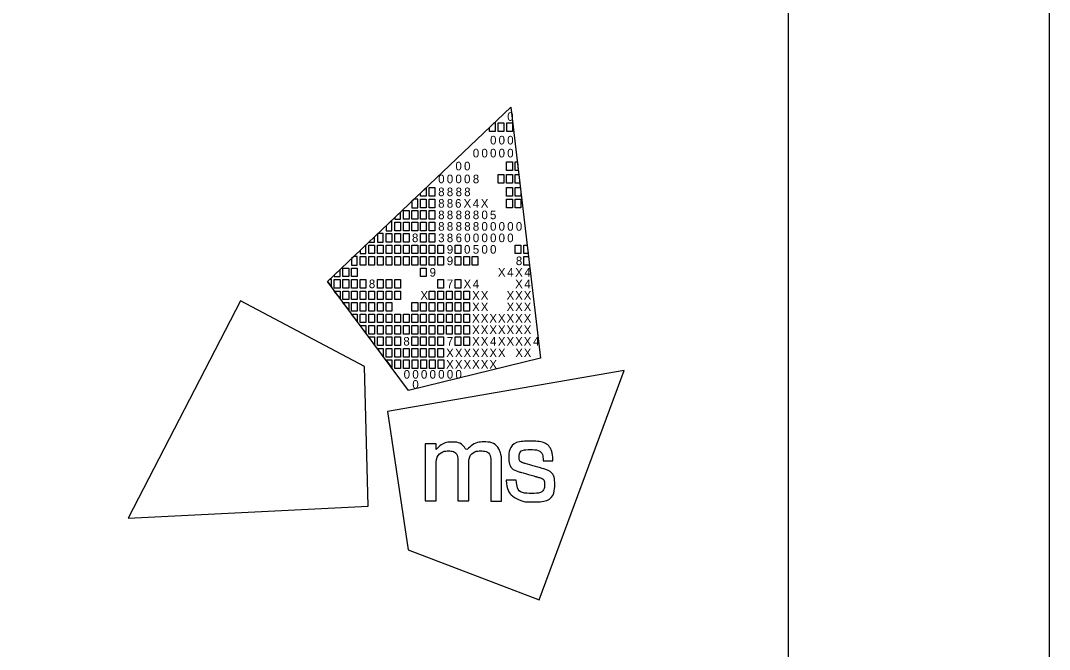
# Model space of a CAD drawing. Extents: x 22.7 to 63.9, y 8.1 to 30.1.
# Drawn here: x 54.689 to 56.659, y 11.605 to 12.81 of the extents above; entities that cross this region are included whole.
import ezdxf

# ---------------------------------------------------------------- set-up
doc = ezdxf.new("R2010")
doc.units = 0
for name, color, linetype in [('SH_Border', 7, 'Continuous'), ('SH_Cut_Line', 7, 'Continuous'), ('SH_Data', 7, 'Continuous')]:
    doc.layers.add(name, color=color, linetype=linetype)

msp = doc.modelspace()

# ---------------------------------------------------------------- linework, layer by layer
at = {"layer": 'SH_Border'}
for p, q in [((55.2765, 12.3096), (55.6277, 12.6438)), ((55.6277, 12.6438), (55.6277, 12.6438)), ((55.6277, 12.6438), (55.6842, 12.1628)), ((55.4319, 12.1007), (55.2765, 12.3096)), ((55.6842, 12.1628), (55.4319, 12.1007))]:
    msp.add_line(p, q, dxfattribs=at)
for points in [[(24.1589, 29.5577), (56.1589, 29.5577), (56.1589, 8.5577), (24.1589, 8.5577)], [(55.5868, 12.6049), (55.5958, 12.6135), (55.5978, 12.6135), (55.5978, 12.5969), (55.5868, 12.5969)], [(55.6033, 12.6135), (55.6143, 12.6135), (55.6143, 12.5969), (55.6033, 12.5969)], [(55.6198, 12.6135), (55.6308, 12.6135), (55.6308, 12.5969), (55.6198, 12.5969)], [(55.6195, 12.5391), (55.6305, 12.5391), (55.6305, 12.5226), (55.6195, 12.5226)], [(55.636, 12.5391), (55.64, 12.5391), (55.6419, 12.5226), (55.636, 12.5226)], [(55.603, 12.5144), (55.614, 12.5144), (55.614, 12.4979), (55.603, 12.4979)], [(55.6195, 12.5144), (55.6305, 12.5144), (55.6305, 12.4979), (55.6195, 12.4979)], [(55.636, 12.5144), (55.6429, 12.5144), (55.6448, 12.4979), (55.636, 12.4979)], [(55.4543, 12.4788), (55.4653, 12.4893), (55.4653, 12.4731), (55.4543, 12.4731)], [(55.4712, 12.4896), (55.4822, 12.4896), (55.4822, 12.4731), (55.4712, 12.4731)], [(55.6195, 12.4896), (55.6305, 12.4896), (55.6305, 12.4731), (55.6195, 12.4731)], [(55.636, 12.4896), (55.6458, 12.4896), (55.647, 12.4795), (55.647, 12.4731), (55.636, 12.4731)], [(55.4547, 12.4676), (55.4657, 12.4676), (55.4657, 12.4511), (55.4547, 12.4511)], [(55.4712, 12.4676), (55.4822, 12.4676), (55.4822, 12.4511), (55.4712, 12.4511)], [(55.6195, 12.4676), (55.6305, 12.4676), (55.6305, 12.4511), (55.6195, 12.4511)], [(55.636, 12.4676), (55.647, 12.4676), (55.647, 12.4511), (55.636, 12.4511)], [(55.4217, 12.4456), (55.4327, 12.4456), (55.4327, 12.4291), (55.4217, 12.4291)], [(55.4382, 12.4456), (55.4492, 12.4456), (55.4492, 12.4291), (55.4382, 12.4291)], [(55.4547, 12.4456), (55.4657, 12.4456), (55.4657, 12.4291), (55.4547, 12.4291)], [(55.4712, 12.4456), (55.4822, 12.4456), (55.4822, 12.4291), (55.4712, 12.4291)], [(55.4051, 12.4236), (55.4162, 12.4236), (55.4162, 12.407), (55.4051, 12.407)], [(55.4217, 12.4236), (55.4327, 12.4236), (55.4327, 12.407), (55.4217, 12.407)], [(55.4382, 12.4236), (55.4492, 12.4236), (55.4492, 12.407), (55.4382, 12.407)], [(55.4547, 12.4236), (55.4657, 12.4236), (55.4657, 12.407), (55.4547, 12.407)], [(55.4712, 12.4236), (55.4822, 12.4236), (55.4822, 12.407), (55.4712, 12.407)], [(55.3886, 12.4015), (55.3996, 12.4015), (55.3996, 12.385), (55.3886, 12.385)], [(55.4051, 12.4015), (55.4162, 12.4015), (55.4162, 12.385), (55.4051, 12.385)], [(55.4217, 12.4015), (55.4327, 12.4015), (55.4327, 12.385), (55.4217, 12.385)], [(55.4547, 12.4015), (55.4657, 12.4015), (55.4657, 12.385), (55.4547, 12.385)], [(55.4712, 12.4015), (55.4822, 12.4015), (55.4822, 12.385), (55.4712, 12.385)], [(55.3556, 12.3795), (55.3666, 12.3795), (55.3666, 12.363), (55.3556, 12.363)], [(55.3721, 12.3795), (55.3831, 12.3795), (55.3831, 12.363), (55.3721, 12.363)], [(55.3886, 12.3795), (55.3996, 12.3795), (55.3996, 12.363), (55.3886, 12.363)], [(55.4051, 12.3795), (55.4162, 12.3795), (55.4162, 12.363), (55.4051, 12.363)], [(55.4217, 12.3795), (55.4327, 12.3795), (55.4327, 12.363), (55.4217, 12.363)], [(55.4382, 12.3795), (55.4492, 12.3795), (55.4492, 12.363), (55.4382, 12.363)], [(55.4547, 12.3795), (55.4657, 12.3795), (55.4657, 12.363), (55.4547, 12.363)], [(55.4712, 12.3795), (55.4822, 12.3795), (55.4822, 12.363), (55.4712, 12.363)], [(55.4877, 12.3795), (55.4987, 12.3795), (55.4987, 12.363), (55.4877, 12.363)], [(55.5207, 12.3795), (55.5317, 12.3795), (55.5317, 12.363), (55.5207, 12.363)], [(55.636, 12.3795), (55.647, 12.3795), (55.647, 12.363), (55.636, 12.363)], [(55.6525, 12.3795), (55.6587, 12.3795), (55.6607, 12.363), (55.6525, 12.363)], [(55.3391, 12.3575), (55.3501, 12.3575), (55.3501, 12.341), (55.3391, 12.341)], [(55.3556, 12.3575), (55.3666, 12.3575), (55.3666, 12.341), (55.3556, 12.341)], [(55.3721, 12.3575), (55.3831, 12.3575), (55.3831, 12.341), (55.3721, 12.341)], [(55.3886, 12.3575), (55.3996, 12.3575), (55.3996, 12.341), (55.3886, 12.341)], [(55.4051, 12.3575), (55.4162, 12.3575), (55.4162, 12.341), (55.4051, 12.341)], [(55.4217, 12.3575), (55.4327, 12.3575), (55.4327, 12.341), (55.4217, 12.341)], [(55.4382, 12.3575), (55.4492, 12.3575), (55.4492, 12.341), (55.4382, 12.341)], [(55.4547, 12.3575), (55.4657, 12.3575), (55.4657, 12.341), (55.4547, 12.341)], [(55.4712, 12.3575), (55.4822, 12.3575), (55.4822, 12.341), (55.4712, 12.341)], [(55.4877, 12.3575), (55.4987, 12.3575), (55.4987, 12.341), (55.4877, 12.341)], [(55.5207, 12.3575), (55.5317, 12.3575), (55.5317, 12.341), (55.5207, 12.341)], [(55.5373, 12.3575), (55.5483, 12.3575), (55.5483, 12.341), (55.5373, 12.341)], [(55.5536, 12.3575), (55.5646, 12.3575), (55.5646, 12.341), (55.5536, 12.341)], [(55.6525, 12.3575), (55.6613, 12.3575), (55.6633, 12.341), (55.6525, 12.341)], [(55.3061, 12.3355), (55.3171, 12.3355), (55.3171, 12.319), (55.3061, 12.319)], [(55.3226, 12.3355), (55.3336, 12.3355), (55.3336, 12.319), (55.3226, 12.319)], [(55.4547, 12.3355), (55.4657, 12.3355), (55.4657, 12.319), (55.4547, 12.319)], [(55.2895, 12.3135), (55.3006, 12.3135), (55.3006, 12.2969), (55.2895, 12.2969)], [(55.3061, 12.3135), (55.3171, 12.3135), (55.3171, 12.2969), (55.3061, 12.2969)], [(55.3226, 12.3135), (55.3336, 12.3135), (55.3336, 12.2969), (55.3226, 12.2969)], [(55.3391, 12.3135), (55.3501, 12.3135), (55.3501, 12.2969), (55.3391, 12.2969)], [(55.3721, 12.3135), (55.3831, 12.3135), (55.3831, 12.2969), (55.3721, 12.2969)], [(55.3886, 12.3135), (55.3996, 12.3135), (55.3996, 12.2969), (55.3886, 12.2969)], [(55.4051, 12.3135), (55.4162, 12.3135), (55.4162, 12.2969), (55.4051, 12.2969)], [(55.4877, 12.3135), (55.4987, 12.3135), (55.4987, 12.2969), (55.4877, 12.2969)], [(55.5207, 12.3135), (55.5317, 12.3135), (55.5317, 12.2969), (55.5207, 12.2969)], [(55.2895, 12.2914), (55.3006, 12.2914), (55.3006, 12.2777)], [(55.3061, 12.2914), (55.3171, 12.2914), (55.3171, 12.2749), (55.3061, 12.2749)], [(55.3226, 12.2914), (55.3336, 12.2914), (55.3336, 12.2749), (55.3226, 12.2749)], [(55.3391, 12.2914), (55.3501, 12.2914), (55.3501, 12.2749), (55.3391, 12.2749)], [(55.3556, 12.2914), (55.3666, 12.2914), (55.3666, 12.2749), (55.3556, 12.2749)], [(55.3721, 12.2914), (55.3831, 12.2914), (55.3831, 12.2749), (55.3721, 12.2749)], [(55.3886, 12.2914), (55.3996, 12.2914), (55.3996, 12.2749), (55.3886, 12.2749)], [(55.4051, 12.2914), (55.4162, 12.2914), (55.4162, 12.2749), (55.4051, 12.2749)], [(55.4712, 12.2914), (55.4822, 12.2914), (55.4822, 12.2749), (55.4712, 12.2749)], [(55.4877, 12.2914), (55.4987, 12.2914), (55.4987, 12.2749), (55.4877, 12.2749)], [(55.5042, 12.2914), (55.5152, 12.2914), (55.5152, 12.2749), (55.5042, 12.2749)], [(55.5207, 12.2914), (55.5317, 12.2914), (55.5317, 12.2749), (55.5207, 12.2749)], [(55.5373, 12.2914), (55.5483, 12.2914), (55.5483, 12.2749), (55.5373, 12.2749)], [(55.3061, 12.2694), (55.3171, 12.2694), (55.3171, 12.2557)], [(55.3226, 12.2694), (55.3336, 12.2694), (55.3336, 12.2529), (55.3226, 12.2529)], [(55.3391, 12.2694), (55.3501, 12.2694), (55.3501, 12.2529), (55.3391, 12.2529)], [(55.3556, 12.2694), (55.3666, 12.2694), (55.3666, 12.2529), (55.3556, 12.2529)], [(55.3721, 12.2694), (55.3831, 12.2694), (55.3831, 12.2529), (55.3721, 12.2529)], [(55.3886, 12.2694), (55.3996, 12.2694), (55.3996, 12.2529), (55.3886, 12.2529)], [(55.4382, 12.2694), (55.4492, 12.2694), (55.4492, 12.2529), (55.4382, 12.2529)], [(55.4547, 12.2694), (55.4657, 12.2694), (55.4657, 12.2529), (55.4547, 12.2529)], [(55.4712, 12.2694), (55.4822, 12.2694), (55.4822, 12.2529), (55.4712, 12.2529)], [(55.4877, 12.2694), (55.4987, 12.2694), (55.4987, 12.2529), (55.4877, 12.2529)], [(55.5042, 12.2694), (55.5152, 12.2694), (55.5152, 12.2529), (55.5042, 12.2529)], [(55.5207, 12.2694), (55.5317, 12.2694), (55.5317, 12.2529), (55.5207, 12.2529)], [(55.5373, 12.2694), (55.5483, 12.2694), (55.5483, 12.2529), (55.5373, 12.2529)], [(55.3226, 12.2474), (55.3336, 12.2474), (55.3336, 12.2336)], [(55.3336, 12.2474), (55.3336, 12.2474), (55.3336, 12.2474)], [(55.3391, 12.2474), (55.3501, 12.2474), (55.3501, 12.2309), (55.3391, 12.2309)], [(55.3556, 12.2474), (55.3666, 12.2474), (55.3666, 12.2309), (55.3556, 12.2309)], [(55.3721, 12.2474), (55.3831, 12.2474), (55.3831, 12.2309), (55.3721, 12.2309)], [(55.3886, 12.2474), (55.3996, 12.2474), (55.3996, 12.2309), (55.3886, 12.2309)], [(55.4051, 12.2474), (55.4162, 12.2474), (55.4162, 12.2309), (55.4051, 12.2309)], [(55.4217, 12.2474), (55.4327, 12.2474), (55.4327, 12.2309), (55.4217, 12.2309)], [(55.4382, 12.2474), (55.4492, 12.2474), (55.4492, 12.2309), (55.4382, 12.2309)], [(55.4547, 12.2474), (55.4657, 12.2474), (55.4657, 12.2309), (55.4547, 12.2309)], [(55.4712, 12.2474), (55.4822, 12.2474), (55.4822, 12.2309), (55.4712, 12.2309)], [(55.4877, 12.2474), (55.4987, 12.2474), (55.4987, 12.2309), (55.4877, 12.2309)], [(55.5042, 12.2474), (55.5152, 12.2474), (55.5152, 12.2309), (55.5042, 12.2309)], [(55.5207, 12.2474), (55.5317, 12.2474), (55.5317, 12.2309), (55.5207, 12.2309)], [(55.5373, 12.2474), (55.5483, 12.2474), (55.5483, 12.2309), (55.5373, 12.2309)], [(55.3391, 12.2254), (55.3501, 12.2254), (55.3501, 12.2116)], [(55.3556, 12.2254), (55.3666, 12.2254), (55.3666, 12.2089), (55.3556, 12.2089)], [(55.3721, 12.2254), (55.3831, 12.2254), (55.3831, 12.2089), (55.3721, 12.2089)], [(55.3886, 12.2254), (55.3996, 12.2254), (55.3996, 12.2089), (55.3886, 12.2089)], [(55.4051, 12.2254), (55.4162, 12.2254), (55.4162, 12.2089), (55.4051, 12.2089)], [(55.4217, 12.2254), (55.4327, 12.2254), (55.4327, 12.2089), (55.4217, 12.2089)], [(55.4382, 12.2254), (55.4492, 12.2254), (55.4492, 12.2089), (55.4382, 12.2089)], [(55.4547, 12.2254), (55.4657, 12.2254), (55.4657, 12.2089), (55.4547, 12.2089)], [(55.4712, 12.2254), (55.4822, 12.2254), (55.4822, 12.2089), (55.4712, 12.2089)], [(55.4877, 12.2254), (55.4987, 12.2254), (55.4987, 12.2089), (55.4877, 12.2089)], [(55.5042, 12.2254), (55.5152, 12.2254), (55.5152, 12.2089), (55.5042, 12.2089)], [(55.5207, 12.2254), (55.5317, 12.2254), (55.5317, 12.2089), (55.5207, 12.2089)], [(55.5373, 12.2254), (55.5483, 12.2254), (55.5483, 12.2089), (55.5373, 12.2089)], [(55.3667, 12.1882), (55.3555, 12.2034), (55.3667, 12.2034)], [(55.3721, 12.2034), (55.3831, 12.2034), (55.3831, 12.1869), (55.3721, 12.1869)], [(55.3886, 12.2034), (55.3996, 12.2034), (55.3996, 12.1869), (55.3886, 12.1869)], [(55.4051, 12.2034), (55.4162, 12.2034), (55.4162, 12.1869), (55.4051, 12.1869)], [(55.4382, 12.2034), (55.4492, 12.2034), (55.4492, 12.1869), (55.4382, 12.1869)], [(55.4547, 12.2034), (55.4657, 12.2034), (55.4657, 12.1869), (55.4547, 12.1869)], [(55.4712, 12.2034), (55.4822, 12.2034), (55.4822, 12.1869), (55.4712, 12.1869)], [(55.4877, 12.2034), (55.4987, 12.2034), (55.4987, 12.1869), (55.4877, 12.1869)], [(55.5207, 12.2034), (55.5317, 12.2034), (55.5317, 12.1869), (55.5207, 12.1869)], [(55.5373, 12.2034), (55.5483, 12.2034), (55.5483, 12.1869), (55.5373, 12.1869)], [(55.3829, 12.1659), (55.3721, 12.1814), (55.3831, 12.1814)], [(55.3886, 12.1813), (55.3996, 12.1813), (55.3996, 12.1648), (55.3886, 12.1648)], [(55.4051, 12.1813), (55.4162, 12.1813), (55.4162, 12.1648), (55.4051, 12.1648)], [(55.4217, 12.1813), (55.4327, 12.1813), (55.4327, 12.1648), (55.4217, 12.1648)], [(55.4382, 12.1813), (55.4492, 12.1813), (55.4492, 12.1648), (55.4382, 12.1648)], [(55.4547, 12.1813), (55.4657, 12.1813), (55.4657, 12.1648), (55.4547, 12.1648)], [(55.4712, 12.1813), (55.4822, 12.1813), (55.4822, 12.1648), (55.4712, 12.1648)], [(55.4877, 12.1813), (55.4987, 12.1813), (55.4987, 12.1648), (55.4877, 12.1648)], [(55.3891, 12.1594), (55.3996, 12.1594), (55.3997, 12.1452)], [(55.4052, 12.1594), (55.4162, 12.1594), (55.4162, 12.1429), (55.4052, 12.1429)], [(55.4219, 12.1594), (55.4329, 12.1594), (55.4329, 12.1429), (55.4219, 12.1429)], [(55.4383, 12.1594), (55.4493, 12.1594), (55.4493, 12.1429), (55.4383, 12.1429)], [(55.4549, 12.1594), (55.466, 12.1594), (55.466, 12.1429), (55.4549, 12.1429)], [(55.4719, 12.1593), (55.4829, 12.1593), (55.4829, 12.1428), (55.4719, 12.1428)], [(55.4885, 12.1593), (55.4995, 12.1593), (55.4995, 12.1428), (55.4885, 12.1428)]]:
    msp.add_lwpolyline(points, close=True, dxfattribs=at)
for points in [[(55.4492, 12.4676), (55.4425, 12.4676), (55.4382, 12.4635), (55.4382, 12.4511), (55.4492, 12.4511), (55.4492, 12.4676)], [(55.4162, 12.4425), (55.4051, 12.4321), (55.4051, 12.4291), (55.4162, 12.4291), (55.4162, 12.4425)], [(55.3996, 12.4268), (55.3886, 12.4163), (55.3886, 12.407), (55.3996, 12.407), (55.3996, 12.4268)], [(55.3666, 12.3954), (55.3557, 12.385), (55.3666, 12.385), (55.3666, 12.3954)], [(55.3831, 12.4015), (55.3731, 12.4015), (55.3721, 12.4006), (55.3721, 12.385), (55.3831, 12.385), (55.3831, 12.4015)], [(55.3501, 12.3797), (55.3391, 12.3692), (55.3391, 12.363), (55.3501, 12.363), (55.3501, 12.3797)], [(55.3336, 12.3575), (55.3268, 12.3575), (55.3226, 12.3535), (55.3226, 12.341), (55.3336, 12.341), (55.3336, 12.3575)], [(55.3006, 12.3325), (55.2895, 12.3221), (55.2895, 12.319), (55.3006, 12.319), (55.3006, 12.3325)], [(55.284, 12.3135), (55.2805, 12.3135), (55.2765, 12.3096), (55.284, 12.2994), (55.284, 12.3135)], [(55.1101, 12.2725), (54.8948, 11.8565), (55.3545, 11.8791), (55.3473, 12.1468), (55.1101, 12.2725)], [(55.6818, 11.6999), (55.8448, 12.1391), (55.3913, 12.0606), (55.4311, 11.7958), (55.6818, 11.6999)]]:
    msp.add_lwpolyline(points, dxfattribs=at)
for points in [[(55.4637, 11.8892), (55.4637, 11.8892), (55.4637, 11.9986), (55.4637, 11.9986), (55.4637, 11.9986), (55.4844, 11.9986), (55.4844, 11.9986), (55.4844, 11.9986), (55.4844, 11.9874), (55.4844, 11.9874), (55.4935, 11.9976), (55.5046, 12.0021), (55.5144, 12.0021), (55.5278, 12.0021), (55.5381, 11.9949), (55.5426, 11.9843), (55.5504, 11.9957), (55.5639, 12.0023), (55.5755, 12.0023), (55.5914, 12.0023), (55.604, 11.9927), (55.6083, 11.9789), (55.6083, 11.9789), (55.6083, 11.9789), (55.6083, 11.9788), (55.609, 11.9766), (55.6095, 11.9749), (55.6095, 11.9647), (55.6095, 11.9647), (55.6095, 11.8891), (55.6095, 11.8891), (55.6095, 11.8891), (55.5892, 11.8891), (55.5892, 11.8891), (55.5892, 11.8891), (55.5892, 11.9625), (55.5892, 11.9625), (55.5892, 11.9778), (55.5808, 11.9851), (55.57, 11.9851), (55.5584, 11.9851), (55.5468, 11.9747), (55.5468, 11.9578), (55.5468, 11.9578), (55.5468, 11.8892), (55.5468, 11.8892), (55.5468, 11.8892), (55.5263, 11.8892), (55.5263, 11.8892), (55.5263, 11.8892), (55.5263, 11.9636), (55.5263, 11.9636), (55.5263, 11.978), (55.5177, 11.9851), (55.5086, 11.9851), (55.4973, 11.9851), (55.4843, 11.9747), (55.4843, 11.9539), (55.4843, 11.9539), (55.4843, 11.8892), (55.4843, 11.8892), (55.4843, 11.8892), (55.4637, 11.8892), (55.4637, 11.8892)], [(55.6185, 11.9285), (55.6185, 11.9285), (55.6184, 11.9294), (55.6184, 11.9294), (55.6184, 11.9294), (55.6192, 11.9294), (55.6192, 11.9294), (55.6192, 11.9294), (55.6372, 11.9294), (55.6372, 11.9294), (55.6372, 11.9294), (55.6378, 11.9294), (55.6378, 11.9294), (55.6378, 11.9294), (55.6379, 11.9287), (55.6379, 11.9287), (55.6392, 11.9131), (55.6476, 11.9037), (55.6679, 11.9037), (55.6862, 11.9037), (55.6922, 11.9131), (55.6922, 11.9208), (55.6922, 11.9308), (55.6845, 11.9334), (55.6764, 11.9357), (55.6764, 11.9357), (55.6459, 11.9444), (55.6459, 11.9444), (55.631, 11.9486), (55.6237, 11.9595), (55.6237, 11.9719), (55.6237, 11.988), (55.6357, 12.0038), (55.6641, 12.0038), (55.6937, 12.0038), (55.7078, 11.9862), (55.7078, 11.9671), (55.7078, 11.9671), (55.7078, 11.9664), (55.7078, 11.9664), (55.7078, 11.9664), (55.7071, 11.9664), (55.7071, 11.9664), (55.7071, 11.9664), (55.6901, 11.9664), (55.6901, 11.9664), (55.6901, 11.9664), (55.6894, 11.9664), (55.6894, 11.9664), (55.6894, 11.9664), (55.6894, 11.9671), (55.6894, 11.9671), (55.6891, 11.9785), (55.6816, 11.9876), (55.6645, 11.9876), (55.648, 11.9876), (55.6432, 11.9794), (55.6432, 11.9734), (55.6432, 11.9685), (55.6458, 11.9636), (55.6548, 11.961), (55.6548, 11.961), (55.6844, 11.9525), (55.6844, 11.9525), (55.7051, 11.9465), (55.7116, 11.9354), (55.7116, 11.9216), (55.7116, 11.9039), (55.6999, 11.8875), (55.6676, 11.8875), (55.6541, 11.8875), (55.6466, 11.8898), (55.6412, 11.8925), (55.628, 11.8991), (55.6198, 11.9113), (55.6185, 11.9285)]]:
    msp.add_open_spline(points, degree=3, dxfattribs=at)
at = {"layer": 'SH_Cut_Line'}
msp.add_lwpolyline([(22.6589, 8.0577), (56.6589, 8.0577), (56.6589, 30.0577), (22.6589, 30.0577)], close=True, dxfattribs=at)
at = {"layer": 'SH_Data'}
msp.add_line((55.4089, 12.0577), (55.4089, 12.0577), dxfattribs=at)

# ---------------------------------------------------------------- texts
at = {"layer": 'SH_Border'}
for s, p in [('0', (55.6206, 12.6174)), ('0', (55.5877, 12.5722)), ('0', (55.6041, 12.5722)), ('0', (55.6206, 12.5722)), ('0', (55.5547, 12.5474)), ('0', (55.5712, 12.5474)), ('0', (55.5877, 12.5474)), ('0', (55.6041, 12.5474)), ('0', (55.6206, 12.5474)), ('0', (55.5214, 12.5226)), ('0', (55.5379, 12.5226)), ('0', (55.4884, 12.4979)), ('0', (55.5049, 12.4979)), ('0', (55.5214, 12.4979)), ('0', (55.5379, 12.4979)), ('8', (55.5547, 12.4979)), ('8', (55.4884, 12.4731)), ('8', (55.5049, 12.4731)), ('8', (55.5218, 12.4731)), ('8', (55.5382, 12.4731)), ('8', (55.4884, 12.4511)), ('8', (55.5049, 12.4511)), ('6', (55.5207, 12.4511)), ('X', (55.537, 12.4511)), ('4', (55.5547, 12.4511)), ('X', (55.5699, 12.4511)), ('8', (55.4884, 12.429)), ('8', (55.5049, 12.429)), ('8', (55.5218, 12.429)), ('8', (55.5383, 12.429)), ('8', (55.5547, 12.429)), ('0', (55.5712, 12.429)), ('5', (55.5876, 12.429)), ('8', (55.4884, 12.407)), ('8', (55.5049, 12.407)), ('8', (55.5218, 12.407)), ('8', (55.5383, 12.407)), ('8', (55.5547, 12.407)), ('0', (55.5712, 12.407)), ('0', (55.5877, 12.407)), ('0', (55.6041, 12.407)), ('0', (55.6206, 12.407)), ('0', (55.6371, 12.407)), ('8', (55.4382, 12.385)), ('3', (55.4884, 12.385)), ('8', (55.5049, 12.385)), ('6', (55.5218, 12.385)), ('0', (55.5383, 12.385)), ('0', (55.5547, 12.385)), ('0', (55.5712, 12.385)), ('0', (55.5877, 12.385)), ('0', (55.6041, 12.385)), ('0', (55.6206, 12.385)), ('9', (55.5049, 12.363)), ('0', (55.5379, 12.363)), ('5', (55.5547, 12.363)), ('0', (55.5712, 12.363)), ('0', (55.5877, 12.363)), ('9', (55.5049, 12.341)), ('8', (55.6371, 12.341)), ('9', (55.4719, 12.319)), ('X', (55.6028, 12.319)), ('4', (55.6206, 12.319)), ('X', (55.6358, 12.319)), ('4', (55.6535, 12.319)), ('8', (55.3556, 12.2969)), ('7', (55.5049, 12.2969)), ('X', (55.537, 12.2969)), ('4', (55.5547, 12.2969)), ('X', (55.6358, 12.2969)), ('4', (55.6535, 12.2969)), ('X', (55.4544, 12.2749)), ('X', (55.5534, 12.2749)), ('X', (55.5699, 12.2749)), ('X', (55.6193, 12.2749)), ('X', (55.6358, 12.2749)), ('X', (55.6522, 12.2749)), ('X', (55.5534, 12.2529)), ('X', (55.5699, 12.2529)), ('X', (55.6193, 12.2529)), ('X', (55.6358, 12.2529)), ('X', (55.6522, 12.2529)), ('X', (55.5534, 12.2309)), ('X', (55.5699, 12.2309)), ('X', (55.5864, 12.2309)), ('X', (55.6028, 12.2309)), ('X', (55.6193, 12.2309)), ('X', (55.6358, 12.2309)), ('X', (55.6522, 12.2309)), ('X', (55.5534, 12.2089)), ('X', (55.5699, 12.2089)), ('X', (55.5864, 12.2089)), ('X', (55.6028, 12.2089)), ('X', (55.6193, 12.2089)), ('X', (55.6358, 12.2089)), ('X', (55.6522, 12.2089)), ('8', (55.4217, 12.1869)), ('7', (55.5049, 12.1869)), ('X', (55.5534, 12.1869)), ('X', (55.5699, 12.1869)), ('4', (55.5877, 12.1869)), ('X', (55.6028, 12.1869)), ('X', (55.6193, 12.1869)), ('X', (55.6358, 12.1869)), ('X', (55.6522, 12.1869)), ('4', (55.67, 12.1869)), ('X', (55.5036, 12.1648)), ('X', (55.5205, 12.1648)), ('X', (55.5369, 12.1648)), ('X', (55.5534, 12.1648)), ('X', (55.5699, 12.1648)), ('X', (55.5864, 12.1648)), ('X', (55.6028, 12.1648)), ('X', (55.6361, 12.1648)), ('X', (55.6522, 12.1648)), ('X', (55.5036, 12.1428)), ('X', (55.5205, 12.1428)), ('X', (55.5369, 12.1428)), ('X', (55.5534, 12.1428)), ('X', (55.5699, 12.1428)), ('X', (55.5864, 12.1428)), ('0', (55.4223, 12.1236)), ('0', (55.4389, 12.1236)), ('0', (55.4554, 12.1236)), ('0', (55.4719, 12.1236)), ('0', (55.4884, 12.1236)), ('0', (55.5049, 12.1236)), ('0', (55.5214, 12.1236)), ('0', (55.4389, 12.1043))]:
    msp.add_text(s, height=0.0165, rotation=360, dxfattribs=at).set_placement(p)

doc.saveas('drawing.dxf')
